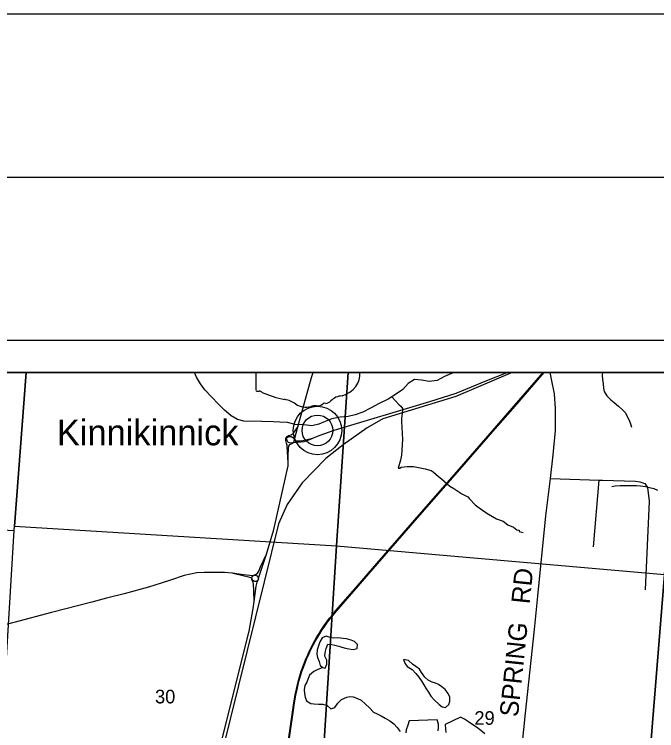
# Model space of a CAD drawing. Extents: x 0 to 34, y 0 to 22.
# Drawn here: x 5.813 to 7.784, y 19.8 to 22 of the extents above; entities that cross this region are included whole.
import ezdxf

# ---------------------------------------------------------------- set-up
doc = ezdxf.new("R2010")
doc.units = 0
for name, color, linetype in [('GM_X_Corporation', 7, 'Continuous'), ('GM_X_County_Road', 7, 'Continuous'), ('GM_X_County_Road_Text', 7, 'Continuous'), ('GM_X_Major_Lake_Text', 7, 'Continuous'), ('GM_X_Minor_Lake', 7, 'Continuous'), ('GM_X_Minor_River', 7, 'Continuous'), ('GM_X_Rail_Line', 7, 'Continuous'), ('GM_X_Section_Text', 7, 'Continuous'), ('GM_X_State_Route', 7, 'Continuous'), ('GM_X_Township_Road', 7, 'Continuous'), ('GM_X_Unincorporated', 7, 'Continuous'), ('GM_X_Unincorporated_Location', 7, 'Continuous'), ('GM_X_Unincorporated_Text', 7, 'Continuous'), ('SH_Border', 7, 'Continuous'), ('SH_Cut_Line', 7, 'Continuous'), ('SH_Data', 7, 'Continuous')]:
    doc.layers.add(name, color=color, linetype=linetype)

msp = doc.modelspace()

# ---------------------------------------------------------------- linework, layer by layer
at = {"layer": 'GM_X_Corporation'}
for p, q in [((8.9, 20.9), (4.9122, 20.9)), ((7.798, 20.9), (6.7774, 20.9))]:
    msp.add_line(p, q, dxfattribs=at)
for points in [[(5.849, 20.9), (4.9193, 20.9), (4.8316, 20.6941), (4.8161, 20.4698), (5.8125, 20.4147), (5.8133, 20.4283)], [(6.8372, 20.9), (5.849, 20.9), (5.8133, 20.4283), (6.802, 20.3679)], [(7.8557, 20.9), (6.8372, 20.9), (6.802, 20.3679), (7.8088, 20.2797)], [(5.8125, 20.4147), (5.8133, 20.4283), (6.802, 20.3679), (6.741, 19.4109), (5.7537, 19.4608)], [(6.802, 20.3679), (7.8088, 20.2797), (7.7331, 19.3433), (6.741, 19.4109)], [(7.8088, 20.2797), (8.8059, 20.2218), (8.7529, 19.294), (7.7331, 19.3433)]]:
    msp.add_lwpolyline(points, close=True, dxfattribs=at)
msp.add_lwpolyline([(8.9, 20.9), (4.892, 20.9)], dxfattribs=at)
at = {"layer": 'GM_X_County_Road'}
msp.add_lwpolyline([(7.3304, 19.3689), (7.3338, 19.386), (7.3468, 19.5088), (7.3626, 19.6642), (7.3815, 19.8538), (7.4091, 20.1111), (7.4196, 20.2137), (7.4445, 20.4597), (7.4584, 20.5745), (7.4672, 20.6478), (7.474, 20.7219), (7.4739, 20.7892), (7.4713, 20.8345), (7.4616, 20.8801), (7.4574, 20.9)], dxfattribs=at)
at = {"layer": 'GM_X_Major_Lake_Text'}
msp.add_lwpolyline([(6.873, 20.9), (6.5542, 20.9), (6.5542, 20.8465)], dxfattribs=at)
for centre, major_axis, start_param, end_param in [((6.786, 20.8932), (0.0874, 0), 5.101753, 6.38063), ((6.558, 20.846), (0.00385, 0), 2.993084, 4.5083), ((6.5586, 20.8665), (0.0294, 0), 4.665946, 4.897461), ((6.5646, 20.8349), (0.0106, 0), 0.519207, 1.627899), ((6.6984, 21.0147), (0.2524, 0), 4.195997, 4.488961), ((6.6232, 20.7566), (0.079, 0), 0.823519, 1.323587), ((6.7622, 20.8271), (0.0282, 0), 4.937069, 5.64225), ((6.8228, 20.7903), (0.0479, 0), 1.647645, 2.488434), ((6.7086, 20.8339), (0.0501, 0), 4.026481, 4.996735), ((6.7375, 20.7648), (0.0412, 0), 1.495662, 1.94098), ((6.7412, 20.819), (0.0267, 0), 4.691044, 5.507374), ((6.7654, 20.7996), (0.00752, 0), 1.147584, 2.315152)]:
    msp.add_ellipse(centre, major_axis=major_axis, ratio=0.8, start_param=start_param, end_param=end_param, dxfattribs=at)
at = {"layer": 'GM_X_Minor_Lake'}
for points in [[(6.7672, 19.9924), (6.7718, 20.0042), (6.7718, 20.0167), (6.7661, 20.0293), (6.7669, 20.0403), (6.7696, 20.0532), (6.7753, 20.0661), (6.7871, 20.0654), (6.797, 20.0627), (6.8087, 20.0604), (6.8182, 20.0569), (6.8292, 20.0535), (6.8399, 20.0512), (6.8528, 20.0493), (6.8653, 20.0531), (6.8661, 20.0652), (6.8566, 20.0744), (6.8464, 20.0785), (6.8327, 20.082), (6.8221, 20.0839), (6.8061, 20.0855), (6.792, 20.0847), (6.7822, 20.0863), (6.7697, 20.0901), (6.7575, 20.0859), (6.751, 20.073), (6.7468, 20.0605), (6.7422, 20.0487), (6.7411, 20.0354), (6.743, 20.0248), (6.749, 20.013), (6.7513, 20.0008)], [(7.0077, 20.0194), (7.0111, 20.008), (7.019, 19.9973), (7.0338, 19.9878), (7.0452, 19.976), (7.0547, 19.9646), (7.0634, 19.9516), (7.0698, 19.941), (7.0774, 19.9284), (7.0846, 19.9182), (7.0918, 19.9064), (7.1028, 19.8938), (7.1164, 19.8805), (7.1263, 19.8736), (7.1358, 19.8717), (7.1468, 19.8808), (7.1499, 19.8907), (7.1495, 19.9028), (7.1446, 19.9146), (7.1351, 19.9268), (7.1249, 19.9352), (7.115, 19.942), (7.1055, 19.9466), (7.0949, 19.9493), (7.0828, 19.9554), (7.0733, 19.9649), (7.0627, 19.9794), (7.0562, 19.9893), (7.0456, 19.9976), (7.0354, 20.0045), (7.0225, 20.0155)], [(7.0225, 20.0155), (7.0077, 20.0194)], [(6.7513, 20.0008), (6.7593, 19.9949), (6.7672, 19.9924)], [(7.1828, 19.842), (7.1353, 19.8196)], [(7.2568, 19.7909), (7.2443, 19.8012), (7.2318, 19.8107), (7.217, 19.8203), (7.2071, 19.8271), (7.1946, 19.8355), (7.1828, 19.842)], [(7.0248, 19.8305), (7.0206, 19.8172), (7.016, 19.8028), (7.0141, 19.7933)], [(7.1107, 19.8341), (7.0248, 19.8305)], [(7.114, 19.7995), (7.1144, 19.8113), (7.1144, 19.8208), (7.1107, 19.8341)], [(7.1353, 19.8196), (7.1361, 19.8052), (7.1376, 19.7953)]]:
    msp.add_lwpolyline(points, dxfattribs=at)
at = {"layer": 'GM_X_Minor_River'}
for points in [[(7.163, 20.9), (7.155, 20.8975), (7.1336, 20.8878), (7.1107, 20.8758), (7.0864, 20.8722), (7.0629, 20.8762), (7.0409, 20.8786), (7.0218, 20.8666), (7.0057, 20.8485), (6.9859, 20.835), (6.9599, 20.8185), (6.9332, 20.805), (6.9065, 20.7908), (6.8821, 20.7788), (6.8593, 20.7706), (6.838, 20.7647), (6.8129, 20.7627), (6.787, 20.7575), (6.7672, 20.7501), (6.7474, 20.7419), (6.7261, 20.7367), (6.7011, 20.7392), (6.6753, 20.741), (6.651, 20.7465), (6.6282, 20.7482), (6.6085, 20.7491), (6.5721, 20.7502), (6.5174, 20.7506), (6.4977, 20.7561), (6.478, 20.7676), (6.4584, 20.7845), (6.4396, 20.8029), (6.4177, 20.8251), (6.3974, 20.8473), (6.3839, 20.8649), (6.3719, 20.8863), (6.3663, 20.9)], [(7.6179, 20.9), (7.6176, 20.8916), (7.6187, 20.8783), (7.6202, 20.865), (7.6217, 20.8524), (7.6236, 20.8418), (7.6315, 20.8289), (7.6433, 20.8167), (7.6539, 20.8083), (7.6672, 20.7973), (7.6801, 20.7858), (7.6884, 20.7763), (7.6944, 20.7649), (7.6994, 20.7554), (7.7028, 20.7459), (7.7077, 20.7322)], [(6.9718, 20.826), (6.9943, 20.801), (6.9996, 20.7964), (7.0045, 20.7892), (7.0045, 20.7865), (7.0037, 20.774), (7.0013, 20.7603), (7.0017, 20.7501), (7.003, 20.7124), (7.0041, 20.6945), (7.0012, 20.6467), (6.9977, 20.6307), (6.9915, 20.6068), (6.9965, 20.6068), (6.9999, 20.6094), (7.0186, 20.6112), (7.0384, 20.6118), (7.0741, 20.6044), (7.0927, 20.5989), (7.098, 20.5951), (7.1147, 20.5813), (7.1245, 20.574), (7.1495, 20.551), (7.1624, 20.5437), (7.1867, 20.5276), (7.2046, 20.5183), (7.2099, 20.5122), (7.2269, 20.4942), (7.2356, 20.4881), (7.2572, 20.472), (7.2678, 20.4651), (7.2929, 20.4508), (7.3134, 20.4439), (7.3274, 20.432), (7.3449, 20.425), (7.3555, 20.4166), (7.362, 20.4158), (7.3627, 20.4116), (7.3745, 20.4089)], [(7.647, 20.5503), (7.6576, 20.5522), (7.6724, 20.5537), (7.688, 20.5536), (7.6994, 20.5532), (7.7127, 20.5532), (7.723, 20.5528), (7.7347, 20.552), (7.7503, 20.5497), (7.7625, 20.5467), (7.7761, 20.5436), (7.7875, 20.539)], [(6.7593, 19.9949), (6.7421, 19.9875), (6.7326, 19.9826), (6.7193, 19.9712), (6.7144, 19.9602), (6.7105, 19.9496), (6.7045, 19.9393), (6.7029, 19.926), (6.704, 19.9146), (6.7055, 19.9036), (6.7093, 19.8918), (6.7226, 19.8838), (6.7325, 19.883), (6.7461, 19.8819), (6.7602, 19.8815), (6.7727, 19.8773), (6.7845, 19.8674), (6.797, 19.8715), (6.8061, 19.8844), (6.8176, 19.8962), (6.8331, 19.903), (6.843, 19.9049), (6.8529, 19.9045), (6.8662, 19.8995), (6.8776, 19.8938), (6.8908, 19.882), (6.9026, 19.871), (6.9155, 19.8573), (6.9261, 19.8523), (6.939, 19.8458), (6.9515, 19.839), (6.9656, 19.831), (6.9777, 19.8214), (6.9883, 19.8104), (6.997, 19.7982)]]:
    msp.add_lwpolyline(points, dxfattribs=at)
at = {"layer": 'GM_X_Rail_Line'}
for points in [[(7.3406, 20.9), (7.1679, 20.8267), (6.9443, 20.7584), (6.8957, 20.7301), (6.8223, 20.6784), (6.7693, 20.6363), (6.6967, 20.5618), (6.6506, 20.4948), (6.6233, 20.4356), (6.5795, 20.2572), (6.397, 19.5172), (6.2733, 19.0197), (6.2341, 18.8804), (6.1559, 18.6926), (6.1001, 18.5873), (6.0785, 18.5248), (6.0655, 18.461), (6.0434, 18.3203), (5.9617, 17.9036), (5.9172, 17.7944), (5.7728, 17.4608), (5.628, 17.1574), (5.5662, 17.0504)], [(6.6468, 19.722), (6.6677, 19.8639), (6.671, 19.8863), (6.675, 19.91), (6.6786, 19.9277), (6.6821, 19.9424), (6.6852, 19.9549), (6.6893, 19.969), (6.6936, 19.9832), (6.7022, 20.0069), (6.7078, 20.0206), (6.7133, 20.0337), (6.7179, 20.0435), (6.7236, 20.0553), (6.7294, 20.0664), (6.7354, 20.0775), (6.7416, 20.0882), (6.7482, 20.0993), (6.756, 20.1112), (6.7641, 20.123), (6.7724, 20.1347), (6.7806, 20.1456), (6.789, 20.156), (6.8, 20.169), (6.8528, 20.2303), (6.9256, 20.3142), (7.0282, 20.4317), (7.1987, 20.627), (7.2803, 20.7206), (7.3411, 20.7905), (7.4365, 20.9)], [(6.6492, 19.7217), (6.6701, 19.8635), (6.6733, 19.886), (6.6774, 19.9095), (6.681, 19.9272), (6.6845, 19.9418), (6.6875, 19.9543), (6.6916, 19.9684), (6.6958, 19.9824), (6.7044, 20.006), (6.7101, 20.0197), (6.7155, 20.0327), (6.7201, 20.0425), (6.7257, 20.0543), (6.7315, 20.0652), (6.7375, 20.0764), (6.7437, 20.087), (6.7502, 20.0981), (6.758, 20.1099), (6.7661, 20.1217), (6.7744, 20.1333), (6.7825, 20.1442), (6.7909, 20.1545), (6.8018, 20.1675), (6.8546, 20.2287), (6.9274, 20.3126), (7.03, 20.4301), (7.2005, 20.6255), (7.2821, 20.719), (7.3429, 20.7889), (7.4396, 20.9)]]:
    msp.add_lwpolyline(points, dxfattribs=at)
at = {"layer": 'GM_X_State_Route'}
for points in [[(6.6834, 20.7331), (6.7254, 20.8844), (6.7306, 20.9)], [(6.727, 20.6978), (6.7331, 20.7007), (6.752, 20.7074), (6.795, 20.7234), (7.088, 20.811), (7.1686, 20.8371), (7.2635, 20.8752), (7.3252, 20.9)], [(6.6532, 20.6231), (6.6536, 20.6457), (6.654, 20.667), (6.6555, 20.674), (6.6589, 20.6794), (6.6648, 20.6822), (6.6705, 20.6862), (6.6726, 20.6943), (6.6834, 20.7331)], [(6.6636, 20.7097), (6.6697, 20.7144), (6.6839, 20.7345)], [(6.65, 20.6773), (6.6487, 20.6834), (6.6459, 20.6911), (6.6464, 20.698), (6.6499, 20.7039), (6.6547, 20.707), (6.6627, 20.709), (6.6636, 20.7097)], [(6.6473, 20.6994), (6.6523, 20.7013), (6.6578, 20.7033), (6.6629, 20.7036), (6.6675, 20.7007), (6.6698, 20.6982), (6.6726, 20.6943)], [(6.6473, 20.6994), (6.6491, 20.6925), (6.6513, 20.6888), (6.6536, 20.6862), (6.6569, 20.6849), (6.6637, 20.6846), (6.6705, 20.6862)], [(6.6726, 20.6943), (6.6748, 20.6919), (6.6793, 20.6903), (6.6838, 20.69), (6.6901, 20.6904), (6.6987, 20.6915), (6.7077, 20.6938), (6.7284, 20.6985)], [(6.6532, 20.6231), (6.6504, 20.6752), (6.65, 20.6773)], [(6.6705, 20.6862), (6.6814, 20.6867), (6.6934, 20.6872), (6.7021, 20.6888), (6.7095, 20.6905), (6.7192, 20.6941), (6.727, 20.6978)], [(6.5872, 20.3428), (6.6093, 20.4184), (6.6532, 20.6136), (6.6532, 20.6231)], [(6.5445, 20.276), (6.5476, 20.2779), (6.551, 20.2794), (6.5556, 20.281), (6.5589, 20.2836), (6.5634, 20.29), (6.5689, 20.3039), (6.5872, 20.3428)], [(6.5487, 20.1966), (6.5555, 20.2446), (6.5582, 20.256), (6.5621, 20.2657), (6.5641, 20.275), (6.5755, 20.3088), (6.5872, 20.3428)], [(6.482, 20.2837), (6.4584, 20.2857), (6.4209, 20.2864), (6.3958, 20.2857), (6.3728, 20.2847), (6.3346, 20.2765), (6.2919, 20.263), (6.2633, 20.2532), (6.2245, 20.2413), (6.1498, 20.2209), (6.0959, 20.2068), (6.0505, 20.1946), (5.9266, 20.1634), (5.6949, 20.1022)], [(6.5446, 20.276), (6.516, 20.2792), (6.483, 20.2836), (6.482, 20.2837)], [(6.5417, 20.2687), (6.5353, 20.2709), (6.4847, 20.2834)], [(6.5417, 20.2687), (6.5427, 20.2731), (6.5445, 20.276)], [(6.5487, 20.1966), (6.5476, 20.2309), (6.5472, 20.2502), (6.5458, 20.2558), (6.5431, 20.2611), (6.5421, 20.2652), (6.5417, 20.2687)], [(6.5621, 20.2657), (6.5602, 20.2614), (6.5575, 20.259), (6.555, 20.2585), (6.5511, 20.2581), (6.5477, 20.2592), (6.5439, 20.2629), (6.5417, 20.2687)], [(6.5621, 20.2657), (6.562, 20.2687), (6.5614, 20.2711), (6.5605, 20.273), (6.559, 20.2747), (6.5561, 20.2763), (6.5533, 20.277), (6.5516, 20.2772), (6.5493, 20.2768), (6.5456, 20.2759), (6.5446, 20.276)], [(6.3653, 19.4317), (6.534, 20.1063), (6.5464, 20.1759), (6.5487, 20.1966)]]:
    msp.add_lwpolyline(points, dxfattribs=at)
at = {"layer": 'GM_X_Township_Road'}
msp.add_line((7.5908, 20.3644), (7.6083, 20.5698), dxfattribs=at)
for points in [[(7.4584, 20.5745), (7.6083, 20.5698), (7.6186, 20.5695)], [(7.6186, 20.5695), (7.719, 20.5666), (7.7333, 20.565), (7.7485, 20.5594), (7.7564, 20.5467), (7.7612, 20.5053), (7.7493, 20.233)]]:
    msp.add_lwpolyline(points, dxfattribs=at)
at = {"layer": 'GM_X_Unincorporated'}
for radius in [0.0744, 0.0472]:
    msp.add_circle((6.7433, 20.7223), radius, dxfattribs=at)
at = {"layer": 'GM_X_Unincorporated_Location'}
msp.add_line((6.7433, 20.7223), (6.7433, 20.7223), dxfattribs=at)
at = {"layer": 'SH_Border'}
msp.add_lwpolyline([(1.5, 21.5), (33.5, 21.5), (33.5, 0.5), (1.5, 0.5)], close=True, dxfattribs=at)
at = {"layer": 'SH_Cut_Line'}
msp.add_lwpolyline([(0, 0), (34, 0), (34, 22), (0, 22)], close=True, dxfattribs=at)
at = {"layer": 'SH_Data'}
for p, q in [((2, 21), (9, 21)), ((2.1, 20.9), (8.9, 20.9))]:
    msp.add_line(p, q, dxfattribs=at)

# ---------------------------------------------------------------- texts
at = {"layer": 'GM_X_County_Road_Text'}
for s, rotation, p in [('RD', 84.0953, (7.3945, 20.1877)), ('SPRING', 84.011, (7.3587, 19.8407))]:
    msp.add_text(s, height=0.05682, rotation=rotation, dxfattribs=at).set_placement(p)
at = {"layer": 'GM_X_Section_Text'}
for s, p in [('30', (6.2447, 19.8842)), ('29', (7.2251, 19.8184))]:
    msp.add_text(s, height=0.04186, rotation=0, dxfattribs=at).set_placement(p)
at = {"layer": 'GM_X_Unincorporated_Text'}
msp.add_text('Kinnikinnick', height=0.078977, rotation=0, dxfattribs=at).set_placement((5.9434, 20.6766))

doc.saveas('drawing.dxf')
